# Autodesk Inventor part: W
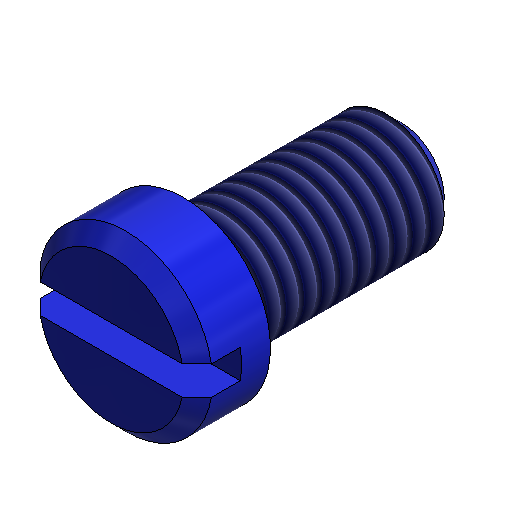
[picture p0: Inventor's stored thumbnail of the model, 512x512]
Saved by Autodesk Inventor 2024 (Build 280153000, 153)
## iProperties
Company: ATC
Shininess: 0.0
Length Units: 11269
Angle Units: 11279
Time Units: 11290
Mass Units: 11283
Length Display Precision: 3
Angle Display Precision: 2
Compacted: True
Created: 2023-03
Part Number: W
Document SubType Name: Modeling
Designer: Andrzej Jaskulski
Material: Kurs-AJ
Density: 1 g/cm^3
Mass: 1.22049 g
Surface Area: 8.1153 cm^2
Volume: 1.22049 cm^3
Appearance: Niebieska — farba ścienna — lśniąca
Checked By: A.J.
Engr Approved By: Andrzej Jaskulski
Mfg Approved By: Andrzej Jaskulski
Authority: A.J.
Density: 0.0
Volumn: 0.0
Area: 0.0
PropertySet Name: Model Information
Control State: 0
Master: False
Checked Out: False
Title: A.J.: Kurs R2024-MEP
Author: Andrzej Jaskulski
Revision Number: 1/24
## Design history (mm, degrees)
node "Extrusion1" dims "d1" = 15, "d2" = 0
node "Extrusion2" dims "d4" = 5, "d5" = 0
node "Chamfer1" dims "d6" = 1, "d7" = 1, "d39" = 45 deg
workplane "Work Plane2"
node "Extrusion3" dims "d11" = 5, "d12" = 0
thread "Thread1" dims "d37" = 10, "d38" = 0
node "Bryła1"
node "Korpusy bryłowe"
node "Korpusy powierzchniowe"
sketch "Sketch1"
  geometry: C1 r 4 at (0, 0)
  constraints: 1 centre point
  dimensions: "d0" = 8 diameter of C1
sketch "Sketch2"
  geometry: C1 r 4 at (0, 0) reference; C2 r 6 at (0, 0)
  constraints: 1 centre point, 1 coincident
  dimensions: "d3" = 12 diameter of C2
sketch "Sketch3"
  geometry: L1 (-1, 5)-(1, 5); L2 (1, 5)-(1, 2); L3 (1, 2)-(-1, 2); L4 (-1, 2)-(-1, 5); L5 (0, 2)-(0, 8)
  constraints: 10 end point, 3 parallel, 1 horizontal, 1 midpoint, 1 perpendicular
  dimensions: "d8" = 3 distance of L1.end L2.end; "d10" = 1 distance between parallel lines of L2 L5
other parameters: "p" = 1.25 [user parameter], "de" = 8 [user parameter], "de1" = 6.647 [user parameter], "de2" = 7.188 [user parameter]
